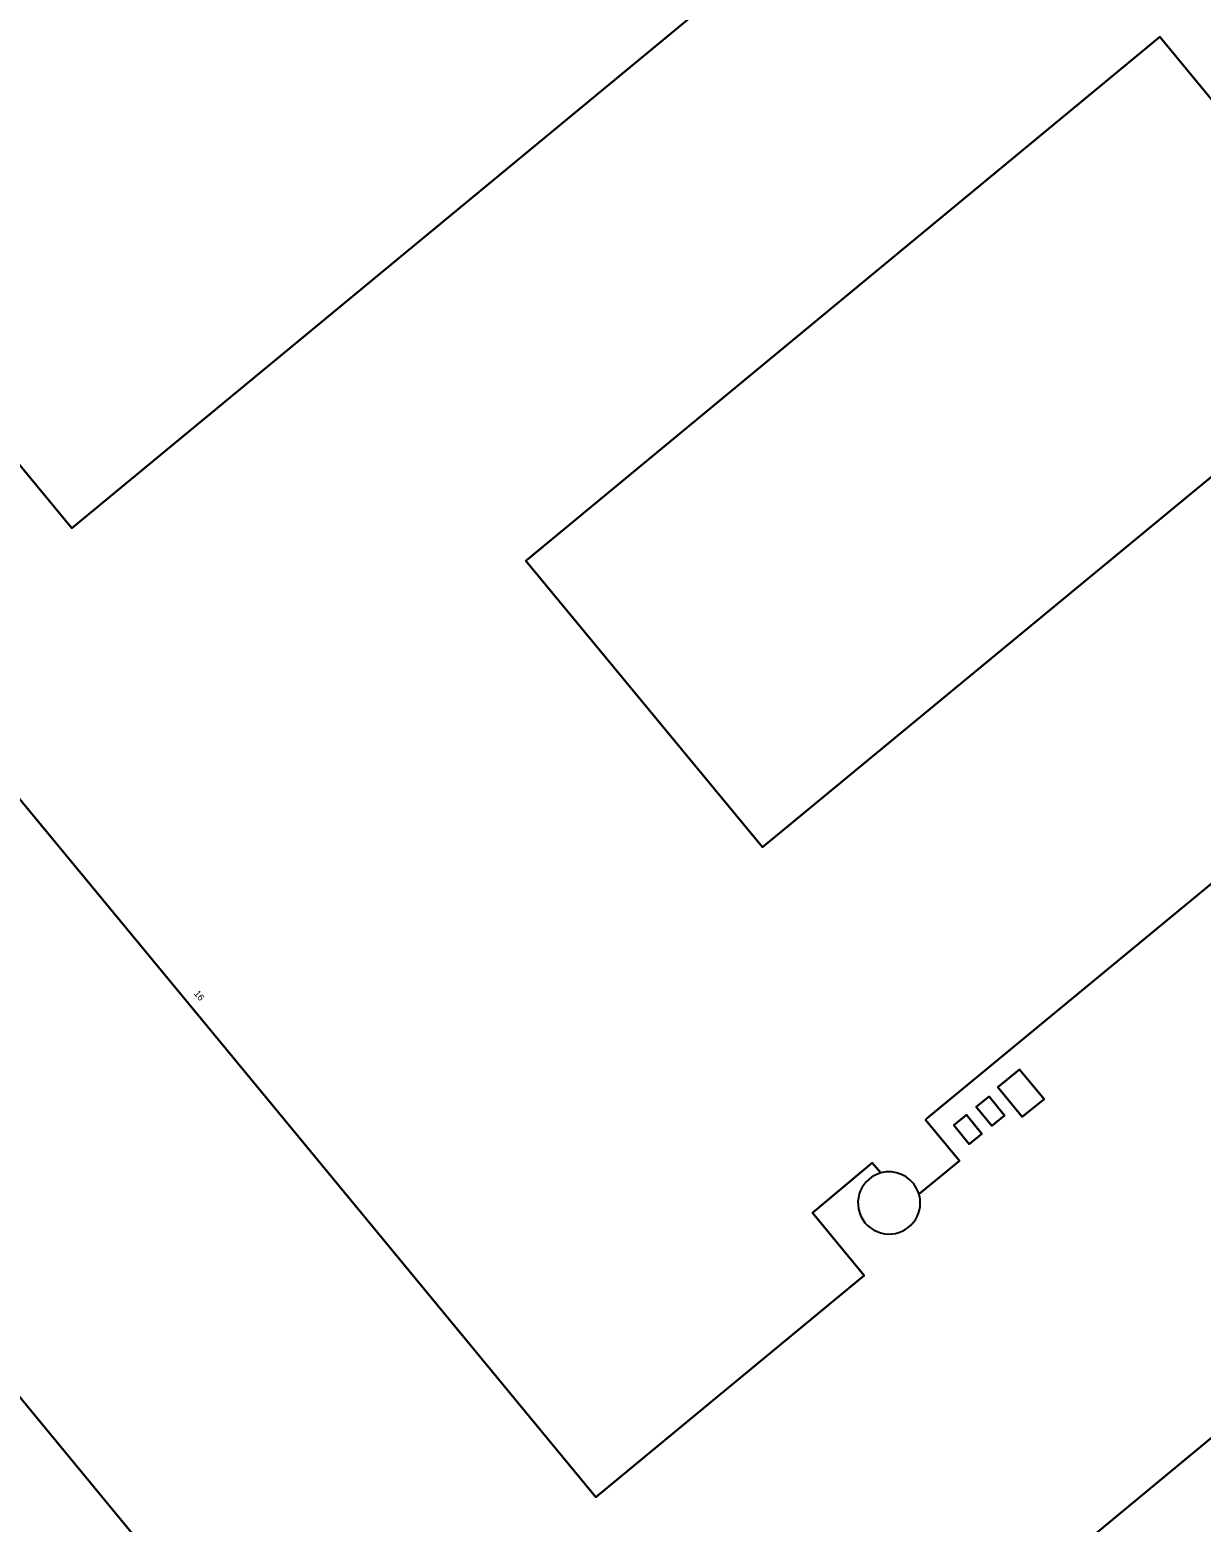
# Model space of a CAD drawing. Extents: x 156141 to 158132, y 385651 to 388333.
# Drawn here: x 157246.8 to 157419.6, y 387051.3 to 387271.6 of the extents above; entities that cross this region are included whole.
import ezdxf

# ---------------------------------------------------------------- set-up
doc = ezdxf.new("R2010")
doc.units = 0
for name, color, linetype in [('IMGEO_Erf', 7, 'Continuous'), ('IMGEO_Hek', 7, 'Continuous'), ('IMGEO_Opslagtank', 7, 'Continuous'), ('IMGEO_Pand', 7, 'Continuous'), ('IMGEO_Pand_nummerreeks', 7, 'Continuous')]:
    doc.layers.add(name, color=color, linetype=linetype)

msp = doc.modelspace()

# ---------------------------------------------------------------- linework, layer by layer
at = {"layer": 'IMGEO_Erf'}
for points in [[(157172.83, 387245.77), (157197.06, 387265.8), (157252.98, 387198.06), (157346.37, 387275.22), (157403.93, 387322.7), (157441.45, 387277.16), (157422.05, 387261.11), (157421.65, 387260.78), (157413.54, 387270.58), (157319.99, 387193.25), (157354.89, 387150.97), (157460.35, 387237.99), (157497.38, 387193.06), (157477.56, 387176.69), (157469.96, 387185.87), (157379.21, 387110.93), (157378.95, 387110.72), (157383.96, 387104.65), (157377.99, 387099.73)], [(157372.36, 387102.86), (157371.11, 387104.35), (157362.29, 387096.97), (157369.92, 387087.72), (157330.32, 387055.02), (157281.16, 387114.57), (157172.83, 387245.77)], [(157471.26, 387105.25), (157329.83, 386988.11), (157257.77, 386928.3), (157274.58, 386907.98), (157277.32, 386904.61), (157284.84, 386895.53), (157300.59, 386876.54), (157345.88, 386821.79), (157383.13, 386776.76), (157405.26, 386750), (157412.6, 386741.13), (157412.85, 386741.41), (157420.47, 386732.25)], [(157329.83, 386988.11), (157471.26, 387105.25)]]:
    msp.add_lwpolyline(points, dxfattribs=at)
for points in [[(157392.85, 387118.14), (157396.45, 387113.74), (157393.22, 387111.13), (157389.63, 387115.51)], [(157388.35, 387114.15), (157390.62, 387111.35), (157388.76, 387109.83), (157386.46, 387112.62)], [(157385.01, 387111.42), (157387.29, 387108.63), (157385.42, 387107.11), (157383.14, 387109.91)], [(157284.07, 387022.73), (157284.01, 387022.68), (157290.93, 387014.33), (157280.32, 387005.53), (157271.05, 387016.78), (157270.95, 387016.71), (157220.25, 387078.2), (157220.31, 387078.25), (157215.63, 387083.89), (157226.26, 387092.72), (157228.64, 387089.8), (157228.72, 387089.86)]]:
    msp.add_lwpolyline(points, close=True, dxfattribs=at)
for centre, radius, start, end in [((157373.59, 387098.44), 4.59, 105.5327, 156.1888), ((157373.58, 387098.43), 4.59, 156.03, 268.4095), ((157373.6, 387098.43), 4.59, 268.1938, 13.505), ((157374.67, 387098.71), 3.47, 13.0491, 16.9989)]:
    msp.add_arc(centre, radius, start, end, dxfattribs=at)
at = {"layer": 'IMGEO_Hek'}
msp.add_lwpolyline([(157257.77, 386928.3), (157329.83, 386988.11), (157471.26, 387105.25), (157625.77, 387233.23)], dxfattribs=at)
at = {"layer": 'IMGEO_Opslagtank'}
for centre, radius, start, end in [((157373.59, 387098.44), 4.59, 105.5327, 156.1888), ((157373.59, 387098.44), 4.59, 27.724, 105.5159), ((157373.58, 387098.43), 4.59, 156.03, 268.4095), ((157373.6, 387098.43), 4.59, 268.1938, 13.505), ((157373.63, 387098.44), 4.55, 16.4218, 27.9281), ((157374.67, 387098.71), 3.47, 13.0491, 16.9989)]:
    msp.add_arc(centre, radius, start, end, dxfattribs=at)
at = {"layer": 'IMGEO_Pand'}
for points in [[(157469.96, 387185.87), (157477.56, 387176.69), (157497.38, 387193.06), (157460.35, 387237.99), (157354.89, 387150.97), (157319.99, 387193.25), (157413.54, 387270.58), (157421.65, 387260.78), (157422.05, 387261.11), (157441.45, 387277.16), (157403.93, 387322.7), (157346.37, 387275.22), (157252.98, 387198.06), (157197.06, 387265.8), (157172.83, 387245.77), (157281.16, 387114.57), (157330.32, 387055.02), (157369.92, 387087.72), (157362.29, 387096.97), (157371.11, 387104.35), (157372.36, 387102.86)], [(157377.99, 387099.73), (157383.96, 387104.65), (157378.95, 387110.72), (157379.21, 387110.93), (157469.96, 387185.87)]]:
    msp.add_lwpolyline(points, dxfattribs=at)
for points in [[(157389.63, 387115.51), (157393.22, 387111.13), (157396.45, 387113.74), (157392.85, 387118.14)], [(157386.46, 387112.62), (157388.76, 387109.83), (157390.62, 387111.35), (157388.35, 387114.15)], [(157385.42, 387107.11), (157387.29, 387108.63), (157385.01, 387111.42), (157383.14, 387109.91)], [(157228.72, 387089.86), (157228.64, 387089.8), (157226.26, 387092.72), (157215.63, 387083.89), (157220.31, 387078.25), (157220.25, 387078.2), (157270.95, 387016.71), (157271.05, 387016.78), (157280.32, 387005.53), (157290.93, 387014.33), (157284.01, 387022.68), (157284.07, 387022.73)]]:
    msp.add_lwpolyline(points, close=True, dxfattribs=at)
for centre, radius, start, end in [((157373.59, 387098.44), 4.59, 27.724, 105.5159), ((157373.63, 387098.44), 4.55, 16.4218, 27.9281)]:
    msp.add_arc(centre, radius, start, end, dxfattribs=at)

# ---------------------------------------------------------------- texts
at = {"layer": 'IMGEO_Pand_nummerreeks'}
msp.add_text('16', height=1, rotation=309.5453, dxfattribs=at).set_placement((157270.93, 387129.32))

doc.saveas('drawing.dxf')
